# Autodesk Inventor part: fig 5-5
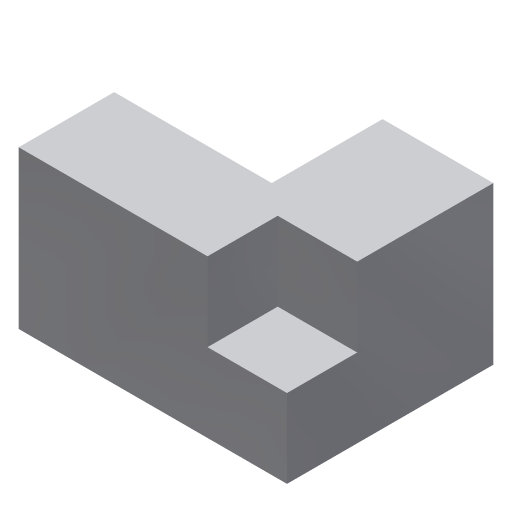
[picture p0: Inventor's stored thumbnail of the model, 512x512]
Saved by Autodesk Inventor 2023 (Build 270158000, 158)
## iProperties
Created: 2010-02
Part Number: fig 5-5
Document SubType Name: Modeling
Designer: CADSoft
Density: 1 g/cm^3
Material: Generic
Appearance: Default
Author: CADSoft
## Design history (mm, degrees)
sketch "Sketch1"
  geometry: L1 (0, 26.227)-(0, 12.145); L2 (0, 12.145)-(-20.026, 12.145); L3 (-20.026, 12.145)-(-20.026, 0); L4 (-20.026, 0)-(14.083, 0); L5 (14.083, 0)-(14.083, 26.227); L6 (14.083, 26.227)-(0, 26.227); 1 further point
  constraints: 12 end point
extrude "Extrusion1" new body sketch "Sketch1" distance "d0" = 20; taper "d1" = 0 deg
sketch "Sketch2"
  geometry: L1 (14.083, 0)-(3.983, 0); L2 (3.983, 0)-(3.983, 8.922); L3 (3.983, 8.922)-(14.083, 8.922); L4 (14.083, 8.922)-(14.083, 0); 1 further point
  constraints: 8 end point
extrude "Extrusion2" cut sketch "Sketch2" distance "d2" = 10; taper "d3" = 0 deg
body "Solid1"
